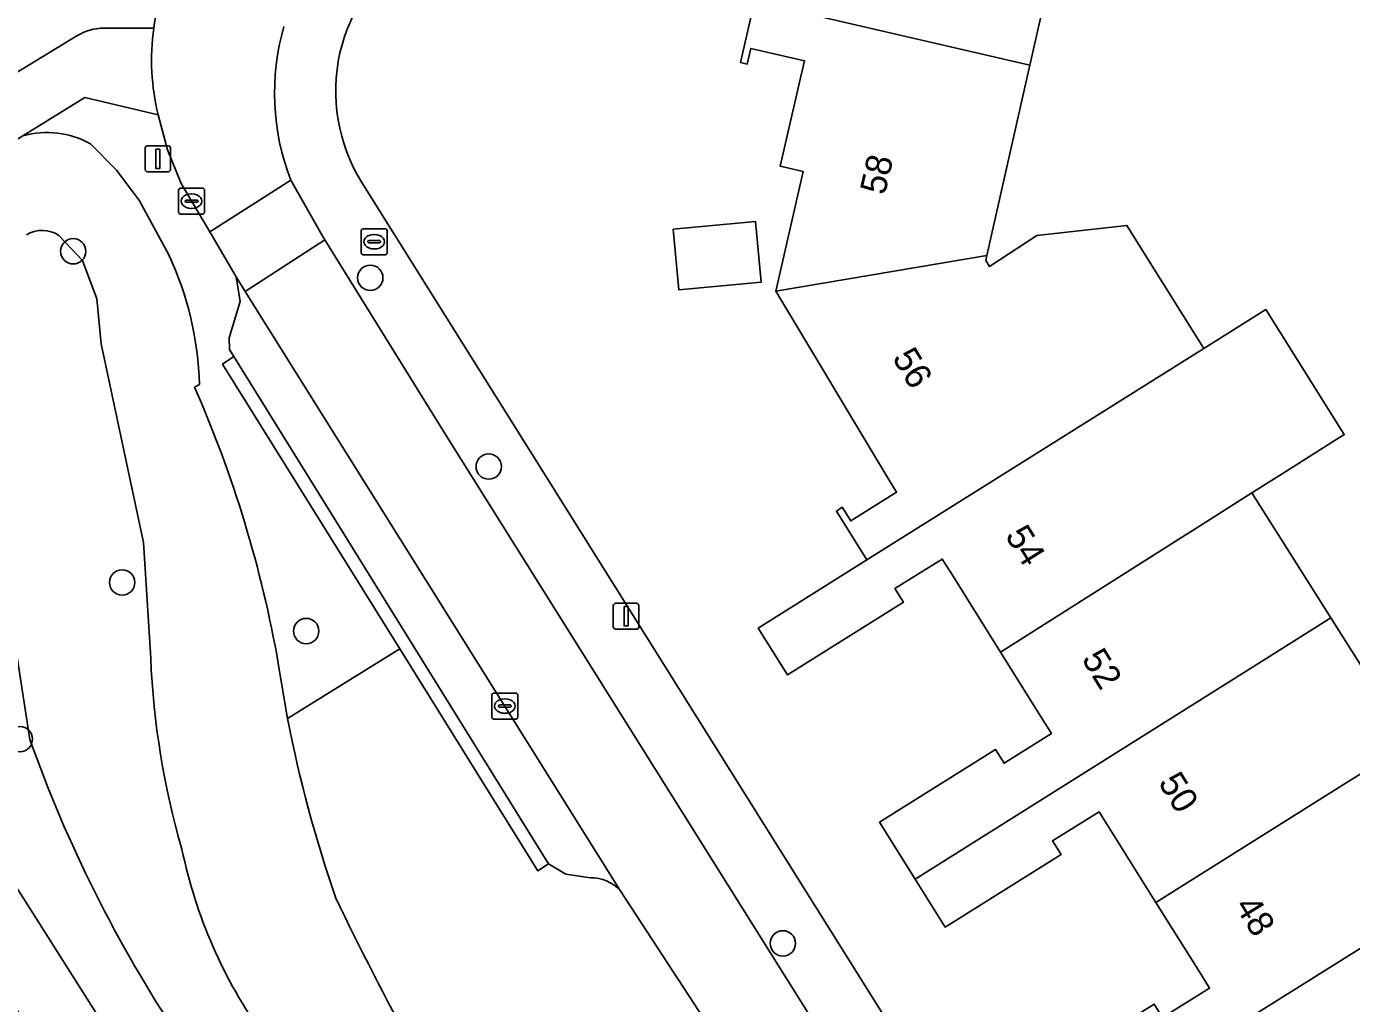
# Model space of a CAD drawing. Extents: x 157767 to 159172, y 387839 to 389425.
# Drawn here: x 158248.5 to 158299.7, y 388185.1 to 388222.8 of the extents above; entities that cross this region are included whole.
import ezdxf

# ---------------------------------------------------------------- set-up
doc = ezdxf.new("R2010")
doc.units = 0
for name, color, linetype in [('IMGEO_Berm_groen', 7, 'Continuous'), ('IMGEO_Boom', 7, 'Continuous'), ('IMGEO_Brandkraan', 7, 'Continuous'), ('IMGEO_Erf', 7, 'Continuous'), ('IMGEO_Fietspad_gesloten', 7, 'Continuous'), ('IMGEO_Groenvoorziening', 7, 'Continuous'), ('IMGEO_Kolk', 7, 'Continuous'), ('IMGEO_Lichtmast', 7, 'Continuous'), ('IMGEO_Pand', 7, 'Continuous'), ('IMGEO_Pand_nummerreeks', 7, 'Continuous'), ('IMGEO_Parkeervlak_open', 7, 'Continuous'), ('IMGEO_Rijbaan_lokaal_open', 7, 'Continuous'), ('IMGEO_Voetpad_open', 7, 'Continuous')]:
    doc.layers.add(name, color=color, linetype=linetype)

msp = doc.modelspace()

# ---------------------------------------------------------------- linework, layer by layer
at = {"layer": 'IMGEO_Berm_groen'}
msp.add_lwpolyline([(158284.447, 388130.761), (158267.054, 388157.932), (158267.593, 388158.305), (158251.677, 388184.006), (158245.465, 388193.775), (158244.861, 388196.895), (158244.443, 388200.045), (158244.365, 388201.777), (158244.402, 388202.182), (158239.306, 388199.147), (158261.497, 388163.28), (158266.953, 388154.792), (158280.022, 388132.677), (158287.415, 388120.635), (158315.068, 388075.588), (158319.468, 388069.305)], dxfattribs=at)
at = {"layer": 'IMGEO_Boom'}
for centre in [(158250.31, 388214.149), (158261.778, 388213.127), (158266.35, 388205.843), (158252.199, 388201.373), (158259.303, 388199.496), (158248.249, 388195.328), (158277.706, 388187.446)]:
    msp.add_circle(centre, 0.489, dxfattribs=at)
at = {"layer": 'IMGEO_Brandkraan'}
for p, q in [((158261.429, 388214.093), (158261.429, 388214.945)), ((158261.504, 388215.019), (158262.356, 388215.019)), ((158262.43, 388214.945), (158262.43, 388214.093)), ((158261.688, 388214.513), (158261.688, 388214.525)), ((158262.126, 388214.476), (158261.728, 388214.476)), ((158261.731, 388214.562), (158262.129, 388214.562)), ((158261.917, 388214.799), (158261.942, 388214.799)), ((158262.172, 388214.525), (158262.172, 388214.513)), ((158262.356, 388214.019), (158261.504, 388214.019)), ((158261.94, 388214.239), (158261.915, 388214.239))]:
    msp.add_line(p, q, dxfattribs=at)
for points in [[(158261.429, 388214.093), (158261.429, 388214.945)], [(158261.504, 388215.019), (158262.356, 388215.019)], [(158262.43, 388214.945), (158262.43, 388214.093)], [(158262.356, 388214.019), (158261.504, 388214.019)]]:
    msp.add_lwpolyline(points, dxfattribs=at)
for centre, radius, start, end in [((158261.506, 388214.943), 0.0765, 91.552, 178.448), ((158261.506, 388214.943), 0.0765, 91.552, 178.448), ((158262.354, 388214.943), 0.0765, 1.552, 88.448), ((158262.354, 388214.943), 0.0765, 1.552, 88.448), ((158261.728, 388214.522), 0.0403, 85.8775, 175.7526), ((158261.725, 388214.512), 0.0366, 178.938, 274.7102), ((158262.129, 388214.519), 0.043, 264.8664, 352.4533), ((158262.133, 388214.524), 0.0386, 1.7309, 96.639), ((158261.506, 388214.095), 0.0765, 181.552, 268.448), ((158261.506, 388214.095), 0.0765, 181.552, 268.448), ((158262.354, 388214.095), 0.0765, 271.552, 358.448), ((158262.354, 388214.095), 0.0765, 271.552, 358.448)]:
    msp.add_arc(centre, radius, start, end, dxfattribs=at)
for centre, major_axis, ratio, start_param, end_param in [((158261.916, 388214.519), (-0.387, 0.002), 0.722429, 4.712389, 7.853982), ((158261.941, 388214.519), (-0.39, 0.002), 0.717154, 1.570796, 4.712389)]:
    msp.add_ellipse(centre, major_axis=major_axis, ratio=ratio, start_param=start_param, end_param=end_param, dxfattribs=at)
at = {"layer": 'IMGEO_Erf'}
for points in [[(158288.882, 388228.585), (158287.241, 388221.328), (158285.582, 388213.989), (158285.537, 388213.792), (158285.678, 388213.567), (158287.513, 388214.764), (158290.986, 388215.147), (158292.361, 388212.95), (158293.959, 388210.397), (158296.356, 388211.9), (158299.38, 388207.078), (158296.984, 388205.563), (158295.817, 388204.825), (158298.865, 388200.005), (158301.921, 388195.173), (158301.957, 388195.196)], [(158292.367, 388184.581), (158294.18, 388185.715), (158293.851, 388186.24), (158292.107, 388189.027), (158290.245, 388192.002), (158289.916, 388192.527), (158288.121, 388191.404), (158288.449, 388190.878), (158283.973, 388188.076), (158282.82, 388189.919), (158281.442, 388192.121), (158285.918, 388194.923), (158286.247, 388194.398), (158288.077, 388195.543), (158287.748, 388196.068), (158286.11, 388198.687), (158284.192, 388201.752), (158283.862, 388202.277), (158282.034, 388201.133), (158282.362, 388200.607), (158277.886, 388197.805), (158276.755, 388199.613), (158280.953, 388202.241), (158279.771, 388204.128), (158280, 388204.271), (158280.329, 388203.747), (158282.096, 388204.852), (158281.776, 388205.382), (158277.43, 388212.613), (158278.492, 388217.224), (158277.604, 388217.429), (158278.403, 388220.897), (158278.543, 388221.503), (158276.469, 388221.981), (158276.329, 388221.375), (158276.065, 388221.436), (158276.607, 388223.785)], [(158261.457, 388216.805), (158334.556, 388100.192)]]:
    msp.add_lwpolyline(points, dxfattribs=at)
msp.add_lwpolyline([(158276.651, 388215.296), (158276.869, 388212.964), (158273.687, 388212.667), (158273.469, 388214.999)], close=True, dxfattribs=at)
msp.add_arc((158267.062, 388220.328), 6.621, 122.1108, 212.1522, dxfattribs=at)
at = {"layer": 'IMGEO_Fietspad_gesloten'}
for points in [[(158248.541, 388225.022), (158239.139, 388219.222), (158234.536, 388216.285), (158235.887, 388213.615), (158242.985, 388217.921), (158250.452, 388222.466)], [(158251.492, 388222.758), (158253.42, 388222.758)]]:
    msp.add_lwpolyline(points, dxfattribs=at)
for centre, radius, start, end in [((158262.674, 388221.474), 9.343, 150.7451, 172.1024), ((158251.49, 388220.769), 1.989, 89.9289, 121.4373)]:
    msp.add_arc(centre, radius, start, end, dxfattribs=at)
at = {"layer": 'IMGEO_Groenvoorziening'}
for points in [[(158256.074, 388209.796), (158256.508, 388210.086), (158256.345, 388210.365), (158256.326, 388210.815), (158256.75, 388212.214), (158256.602, 388213.161), (158255.578, 388214.897), (158254.474, 388216.768), (158253.945, 388218.059), (158253.592, 388219.409), (158250.756, 388220.078), (158248.367, 388218.606)], [(158253.998, 388214.015), (158252.864, 388216.096), (158251.996, 388217.264), (158250.971, 388218.298)], [(158250.971, 388218.298), (158251.996, 388217.264), (158252.864, 388216.096), (158253.998, 388214.015)], [(158253.026, 388202.911), (158251.389, 388210.584), (158251.225, 388212.318), (158250.669, 388213.801), (158249.755, 388214.759)], [(158249.755, 388214.759), (158250.669, 388213.801), (158251.225, 388212.318), (158251.389, 388210.584), (158253.026, 388202.911), (158253.301, 388198.455)], [(158258.226, 388198.244), (158258.586, 388196.124), (158262.917, 388198.808), (158256.074, 388209.796)], [(158254.992, 388208.907), (158255.182, 388209.006)], [(158255.182, 388209.006), (158254.992, 388208.907)], [(158248.636, 388195.307), (158248.014, 388199.321), (158247.195, 388203.3), (158247.09, 388203.784), (158244.402, 388202.182), (158244.365, 388201.777), (158244.443, 388200.045), (158244.861, 388196.895), (158245.465, 388193.775), (158251.677, 388184.006), (158267.593, 388158.305), (158271.655, 388154.023)], [(158247.09, 388203.784), (158247.195, 388203.3), (158248.014, 388199.321), (158248.636, 388195.307)], [(158253.301, 388198.455), (158253.026, 388202.911)], [(158270.279, 388189.976), (158269.321, 388190.117), (158268.663, 388190.518), (158268.252, 388190.24), (158262.917, 388198.808), (158258.586, 388196.124)], [(158258.586, 388196.124), (158258.226, 388198.244)], [(158274.838, 388182.003), (158275.115, 388183.141), (158274.891, 388184.181), (158271.419, 388189.486)]]:
    msp.add_lwpolyline(points, dxfattribs=at)
for centre, radius, start, end in [((158249.294, 388215.282), 3.451, 60.9264, 105.5825), ((158249.294, 388215.282), 3.451, 60.9264, 105.5825), ((158249.113, 388213.825), 1.133, 55.5096, 122.6615), ((158249.113, 388213.825), 1.133, 55.5096, 122.6615), ((158242.558, 388208.666), 12.629, 1.541, 25.0574), ((158242.558, 388208.666), 12.629, 1.541, 25.0574), ((158212.626, 388190.236), 46.298, 9.9606, 23.7836), ((158212.626, 388190.236), 46.298, 9.9606, 23.7836), ((158284.112, 388199.711), 30.836, 182.3338, 196.2478), ((158284.112, 388199.711), 30.836, 182.3338, 196.2478), ((158307.409, 388205.531), 49.721, 190.9056, 199.1905), ((158307.409, 388205.531), 49.721, 190.9056, 199.1905), ((158298.159, 388212.967), 52.578, 199.6264, 213.6158), ((158298.159, 388212.967), 52.578, 199.6264, 213.6158), ((158273.15, 388194.958), 19.041, 191.7433, 215.4744), ((158273.15, 388194.958), 19.041, 191.7433, 215.4744), ((158270.302, 388188.459), 1.518, 42.6093, 90.8723), ((158359.524, 388236.545), 109.81, 205.54854, 212.29451), ((158359.524, 388236.545), 109.81, 205.54854, 212.29451)]:
    msp.add_arc(centre, radius, start, end, dxfattribs=at)
at = {"layer": 'IMGEO_Kolk'}
for p, q in [((158254.378, 388215.659), (158254.378, 388216.511)), ((158254.453, 388216.585), (158255.305, 388216.585)), ((158254.866, 388216.365), (158254.891, 388216.365)), ((158255.379, 388216.511), (158255.379, 388215.659)), ((158254.637, 388216.079), (158254.637, 388216.091)), ((158255.075, 388216.042), (158254.677, 388216.042)), ((158254.68, 388216.128), (158255.078, 388216.128)), ((158255.121, 388216.091), (158255.121, 388216.079)), ((158255.305, 388215.585), (158254.453, 388215.585)), ((158254.889, 388215.805), (158254.864, 388215.805)), ((158266.471, 388196.176), (158266.471, 388197.028)), ((158266.546, 388197.102), (158267.398, 388197.102)), ((158267.472, 388197.028), (158267.472, 388196.176)), ((158266.73, 388196.596), (158266.73, 388196.608)), ((158267.168, 388196.559), (158266.77, 388196.559)), ((158266.773, 388196.645), (158267.171, 388196.645)), ((158266.959, 388196.882), (158266.984, 388196.882)), ((158267.214, 388196.608), (158267.214, 388196.596)), ((158267.398, 388196.102), (158266.546, 388196.102)), ((158266.982, 388196.322), (158266.957, 388196.322))]:
    msp.add_line(p, q, dxfattribs=at)
for points in [[(158254.378, 388215.659), (158254.378, 388216.511)], [(158254.453, 388216.585), (158255.305, 388216.585)], [(158255.379, 388216.511), (158255.379, 388215.659)], [(158255.305, 388215.585), (158254.453, 388215.585)], [(158266.471, 388196.176), (158266.471, 388197.028)], [(158266.546, 388197.102), (158267.398, 388197.102)], [(158267.472, 388197.028), (158267.472, 388196.176)], [(158267.398, 388196.102), (158266.546, 388196.102)]]:
    msp.add_lwpolyline(points, dxfattribs=at)
for centre, radius, start, end in [((158254.455, 388216.509), 0.0765, 91.552, 178.448), ((158254.455, 388216.509), 0.0765, 91.552, 178.448), ((158255.303, 388216.509), 0.0765, 1.552, 88.448), ((158255.303, 388216.509), 0.0765, 1.552, 88.448), ((158254.677, 388216.088), 0.0403, 85.8775, 175.7526), ((158254.674, 388216.078), 0.0366, 178.938, 274.7102), ((158255.078, 388216.085), 0.043, 264.8664, 352.4533), ((158255.082, 388216.09), 0.0386, 1.7309, 96.639), ((158254.455, 388215.661), 0.0765, 181.552, 268.448), ((158254.455, 388215.661), 0.0765, 181.552, 268.448), ((158255.303, 388215.661), 0.0765, 271.552, 358.448), ((158255.303, 388215.661), 0.0765, 271.552, 358.448), ((158266.548, 388197.026), 0.0765, 91.552, 178.448), ((158266.548, 388197.026), 0.0765, 91.552, 178.448), ((158267.396, 388197.026), 0.0765, 1.552, 88.448), ((158267.396, 388197.026), 0.0765, 1.552, 88.448), ((158266.77, 388196.605), 0.0403, 85.8775, 175.7526), ((158266.767, 388196.595), 0.0366, 178.938, 274.7102), ((158267.171, 388196.602), 0.043, 264.8664, 352.4533), ((158267.175, 388196.607), 0.0386, 1.7309, 96.639), ((158266.548, 388196.178), 0.0765, 181.552, 268.448), ((158266.548, 388196.178), 0.0765, 181.552, 268.448), ((158267.396, 388196.178), 0.0765, 271.552, 358.448), ((158267.396, 388196.178), 0.0765, 271.552, 358.448)]:
    msp.add_arc(centre, radius, start, end, dxfattribs=at)
for centre, major_axis, ratio, start_param, end_param in [((158254.865, 388216.085), (-0.387, 0.002), 0.722429, 4.712389, 7.853982), ((158254.89, 388216.085), (-0.39, 0.002), 0.717154, 1.570796, 4.712389), ((158266.958, 388196.602), (-0.387, 0.002), 0.722429, 4.712389, 7.853982), ((158266.983, 388196.602), (-0.39, 0.002), 0.717154, 1.570796, 4.712389)]:
    msp.add_ellipse(centre, major_axis=major_axis, ratio=ratio, start_param=start_param, end_param=end_param, dxfattribs=at)
at = {"layer": 'IMGEO_Lichtmast'}
for p, q in [((158253.081, 388217.319), (158253.081, 388218.119)), ((158253.081, 388218.119), (158253.081, 388217.319)), ((158253.181, 388218.219), (158253.971, 388218.219)), ((158253.971, 388218.219), (158253.181, 388218.219)), ((158254.071, 388218.119), (158254.071, 388217.319)), ((158254.071, 388217.319), (158254.071, 388218.119)), ((158253.971, 388217.219), (158253.181, 388217.219)), ((158253.181, 388217.219), (158253.971, 388217.219)), ((158271.258, 388200.568), (158272.048, 388200.568)), ((158272.048, 388200.568), (158271.258, 388200.568)), ((158271.158, 388199.668), (158271.158, 388200.468)), ((158271.158, 388200.468), (158271.158, 388199.668)), ((158272.148, 388200.468), (158272.148, 388199.668)), ((158272.148, 388199.668), (158272.148, 388200.468)), ((158272.048, 388199.568), (158271.258, 388199.568)), ((158271.258, 388199.568), (158272.048, 388199.568))]:
    msp.add_line(p, q, dxfattribs=at)
for points in [[(158253.501, 388218.094), (158253.651, 388218.094), (158253.651, 388217.344), (158253.501, 388217.344), (158253.501, 388218.094)], [(158271.578, 388200.443), (158271.728, 388200.443), (158271.728, 388199.693), (158271.578, 388199.693), (158271.578, 388200.443)]]:
    msp.add_lwpolyline(points, dxfattribs=at)
for centre, start, end in [((158253.181, 388218.119), 90, 180), ((158253.181, 388218.119), 90, 180), ((158253.971, 388218.119), 0, 90), ((158253.971, 388218.119), 360, 90), ((158253.181, 388217.319), 180, 270), ((158253.181, 388217.319), 180, 270), ((158253.971, 388217.319), 270, 0), ((158253.971, 388217.319), 270, 0), ((158271.258, 388200.468), 90, 180), ((158271.258, 388200.468), 90, 180), ((158272.048, 388200.468), 0, 90), ((158272.048, 388200.468), 360, 90), ((158271.258, 388199.668), 180, 270), ((158271.258, 388199.668), 180, 270), ((158272.048, 388199.668), 270, 0), ((158272.048, 388199.668), 270, 0)]:
    msp.add_arc(centre, 0.1, start, end, dxfattribs=at)
at = {"layer": 'IMGEO_Pand'}
for points in [[(158287.241, 388221.328), (158288.882, 388228.585), (158288.985, 388228.65), (158282.297, 388233.442), (158281.14, 388228.644), (158280.209, 388228.859), (158279.413, 388225.404), (158279.274, 388224.801), (158277.228, 388225.272), (158277.367, 388225.876), (158277.103, 388225.936), (158276.607, 388223.785)], [(158287.241, 388221.328), (158276.607, 388223.785), (158276.065, 388221.436), (158276.329, 388221.375), (158276.469, 388221.981), (158278.543, 388221.503), (158278.403, 388220.897), (158277.604, 388217.429), (158278.492, 388217.224), (158277.43, 388212.613), (158285.582, 388213.989)], [(158273.469, 388214.999), (158273.687, 388212.667), (158276.869, 388212.964), (158276.651, 388215.296)], [(158293.959, 388210.397), (158292.361, 388212.95), (158290.986, 388215.147), (158287.513, 388214.764), (158285.678, 388213.567), (158285.537, 388213.792), (158285.582, 388213.989), (158277.43, 388212.613), (158281.776, 388205.382), (158282.096, 388204.852), (158280.329, 388203.747), (158280, 388204.271), (158279.771, 388204.128), (158280.953, 388202.241)], [(158293.234, 388203.192), (158293.37, 388203.278), (158295.817, 388204.825), (158296.984, 388205.563), (158299.38, 388207.078), (158296.356, 388211.9), (158293.959, 388210.397), (158280.953, 388202.241), (158276.755, 388199.613), (158277.886, 388197.805), (158282.362, 388200.607), (158282.034, 388201.133), (158283.862, 388202.277), (158284.192, 388201.752), (158286.11, 388198.687)], [(158296.392, 388198.45), (158298.865, 388200.005), (158295.817, 388204.825), (158293.37, 388203.278), (158293.234, 388203.192), (158286.11, 388198.687), (158287.748, 388196.068), (158288.077, 388195.543), (158286.247, 388194.398), (158285.918, 388194.923), (158281.442, 388192.121), (158282.82, 388189.919)], [(158299.421, 388193.609), (158301.921, 388195.173), (158298.865, 388200.005), (158296.392, 388198.45), (158282.82, 388189.919), (158283.973, 388188.076), (158288.449, 388190.878), (158288.121, 388191.404), (158289.916, 388192.527), (158290.245, 388192.002), (158292.107, 388189.027)], [(158305.458, 388183.964), (158305.35, 388184.137), (158302.443, 388188.781), (158288.839, 388180.263), (158290.058, 388178.315), (158294.534, 388181.117), (158294.206, 388181.643), (158295.961, 388182.741), (158296.29, 388182.216), (158298.183, 388179.192), (158298.412, 388179.335), (158298.305, 388179.507), (158300.261, 388180.726)]]:
    msp.add_lwpolyline(points, close=True, dxfattribs=at)
msp.add_lwpolyline([(158301.957, 388195.196), (158301.921, 388195.173), (158299.421, 388193.609), (158292.107, 388189.027), (158293.851, 388186.24), (158294.18, 388185.715), (158292.367, 388184.581), (158292.038, 388185.106), (158287.562, 388182.304), (158288.839, 388180.263), (158302.443, 388188.781)], dxfattribs=at)
at = {"layer": 'IMGEO_Parkeervlak_open'}
msp.add_lwpolyline([(158271.419, 388189.486), (158265.936, 388198.263), (158256.953, 388212.6), (158256.602, 388213.161), (158256.75, 388212.214), (158256.326, 388210.815), (158256.345, 388210.365), (158256.508, 388210.086), (158268.663, 388190.518), (158269.321, 388190.117), (158270.279, 388189.976)], dxfattribs=at)
msp.add_arc((158270.302, 388188.459), 1.518, 42.6093, 90.8723, dxfattribs=at)
at = {"layer": 'IMGEO_Rijbaan_lokaal_open'}
msp.add_lwpolyline([(158253.592, 388219.409), (158253.945, 388218.059), (158254.474, 388216.768), (158255.578, 388214.897), (158258.71, 388216.895)], dxfattribs=at)
for points in [[(158256.953, 388212.6), (158260.026, 388214.59), (158259.906, 388214.783), (158258.71, 388216.895), (158255.578, 388214.897), (158256.602, 388213.161)], [(158256.953, 388212.6), (158265.936, 388198.263), (158271.419, 388189.486), (158274.891, 388184.181), (158283.372, 388170.593), (158286.404, 388172.495), (158282.532, 388178.667), (158279.535, 388183.398), (158270.502, 388197.809), (158264.751, 388206.972), (158260.026, 388214.59)]]:
    msp.add_lwpolyline(points, close=True, dxfattribs=at)
for centre, radius, start, end in [((158262.674, 388221.474), 9.343, 150.7451, 172.1024), ((158262.219, 388221.531), 8.885, 172.0618, 193.8183), ((158267.39, 388220.257), 9.309, 164.0025, 201.1746)]:
    msp.add_arc(centre, radius, start, end, dxfattribs=at)
at = {"layer": 'IMGEO_Voetpad_open'}
for points in [[(158253.42, 388222.758), (158251.492, 388222.758)], [(158250.452, 388222.466), (158242.985, 388217.921), (158235.887, 388213.615), (158235.415, 388213.329)], [(158234.054, 388207.383), (158237.465, 388202.123), (158241.701, 388204.972), (158237.333, 388211.876), (158243.905, 388215.856), (158248.367, 388218.606), (158250.756, 388220.078)], [(158250.756, 388220.078), (158253.592, 388219.409)], [(158258.71, 388216.895), (158259.906, 388214.783), (158260.026, 388214.59), (158264.751, 388206.972), (158270.502, 388197.809), (158279.535, 388183.398), (158282.532, 388178.667), (158286.404, 388172.495), (158287.94, 388170.047), (158302.626, 388146.635), (158317.762, 388122.399), (158332.4, 388098.911)], [(158334.556, 388100.192), (158261.457, 388216.805)]]:
    msp.add_lwpolyline(points, dxfattribs=at)
msp.add_lwpolyline([(158268.663, 388190.518), (158256.508, 388210.086), (158256.074, 388209.796), (158262.917, 388198.808), (158268.252, 388190.24)], close=True, dxfattribs=at)
for centre, radius, start, end in [((158267.062, 388220.328), 6.621, 122.1108, 212.1522), ((158251.49, 388220.769), 1.989, 89.9289, 121.4373), ((158262.219, 388221.531), 8.885, 172.0618, 193.8183), ((158267.39, 388220.257), 9.309, 164.0025, 201.1746)]:
    msp.add_arc(centre, radius, start, end, dxfattribs=at)

# ---------------------------------------------------------------- texts
at = {"layer": 'IMGEO_Pand_nummerreeks'}
for s, rotation, p in [('58', 77.0298, (158281.642, 388216.288)), ('56', 301.1343, (158281.908, 388210.037)), ('54', 301.8161, (158286.264, 388203.179)), ('52', 301.8161, (158289.216, 388198.42)), ('50', 301.8161, (158292.174, 388193.651)), ('48', 301.8161, (158295.129, 388188.889))]:
    msp.add_text(s, height=1, rotation=rotation, dxfattribs=at).set_placement(p)

doc.saveas('drawing.dxf')
